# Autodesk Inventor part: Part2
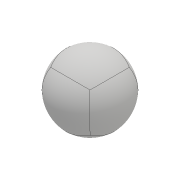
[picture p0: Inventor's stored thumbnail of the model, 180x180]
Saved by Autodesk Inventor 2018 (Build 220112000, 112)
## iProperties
Created: 2015-07
Part Number: Part2
Material: Generic
Document SubType Name: Modeling
Designer: Sandeep
Density: 1 g/cm^3
Appearance: Default
Author: Sandeep
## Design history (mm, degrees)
feature "Form1"
body "Solid1"
